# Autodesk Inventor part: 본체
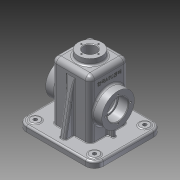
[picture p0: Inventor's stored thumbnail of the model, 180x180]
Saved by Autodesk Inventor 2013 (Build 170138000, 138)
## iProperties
Created: 2016-01
Part Number: 본체
Material: 알루미늄 6061
Document SubType Name: Modeling
Designer: User
Density: 2.71 g/cm^3
Mass: 858.396 g
Surface Area: 910.857 cm^2
Volume: 316.751 cm^3
Author: User
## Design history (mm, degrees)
sketch "스케치1"
  geometry: L1 (-65, -57.5)-(65, -57.5); L2 (65, -57.5)-(65, 57.5); L3 (65, 57.5)-(-65, 57.5); L4 (-65, 57.5)-(-65, -57.5); L5 (-65, -57.5)-(65, 57.5); L6 (65, -57.5)-(-65, 57.5); 1 further point
  constraints: 12 end point, 2 midpoint, 2 parallel, 1 horizontal, 1 perpendicular
  dimensions: "d0" = 130 distance of L2.end L3.end; "d2" = 115 distance of L1.end L2.end
extrude "돌출1" new body sketch "스케치1" distance "d3" = 10; taper "d4" = 0 deg
sketch "스케치2"
  geometry: L1 (-60, -52.5)-(60, -52.5); L2 (60, -52.5)-(60, 52.5); L3 (60, 52.5)-(-60, 52.5); L4 (-60, 52.5)-(-60, -52.5); L5 (-60, -52.5)-(60, 52.5); L6 (60, -52.5)-(-60, 52.5); 1 further point
  constraints: 12 end point, 2 midpoint, 2 parallel, 1 horizontal, 1 perpendicular
  dimensions: "d5" = 120 distance of L2.end L3.end; "d7" = 105 distance of L1.end L2.end
extrude "돌출2" join sketch "스케치2" distance "d8" = 2; taper "d9" = 0 deg
sketch "스케치3"
  geometry: L1 (-32.5, -32.5)-(32.5, -32.5); L2 (32.5, -32.5)-(32.5, 32.5); L3 (32.5, 32.5)-(-32.5, 32.5); L4 (-32.5, 32.5)-(-32.5, -32.5); L5 (-32.5, -32.5)-(32.5, 32.5); L6 (32.5, -32.5)-(-32.5, 32.5); 1 further point
  constraints: 12 end point, 2 midpoint, 2 parallel, 1 horizontal, 1 perpendicular
  dimensions: "d10" = 65 distance of L2.end L3.end; "d12" = 65 distance of L1.end L2.end
extrude "돌출3" join sketch "스케치3" distance "d13" = 98; taper "d14" = 0 deg
sketch "스케치4"
  geometry: C1 r 20 at (0, 0); 1 further point
  constraints: 1 centre point, 1 coincident
  dimensions: "d15" = 40 diameter of C1
extrude "돌출4" join sketch "스케치4" distance "d17" = 10; taper "d18" = 0 deg
feature "면 기울기1" dims angle "d19" = 2.5 deg
sketch "스케치5"
  geometry: C1 r 27.5 at (-43, 32.5); 1 further point
  constraints: 1 centre point, 1 horizontal alignment
  dimensions: "d20" = 55 diameter of C1; "d22" = 53 distance of point (10, 32.5) C1.centre
extrude "돌출5" join sketch "스케치5" distance "d23" = 15; taper "d24" = 0 deg
sketch "스케치7"
  geometry: L1 (32.5, -32.5)-(-32.5, -32.5) reference; L2 (0, 0)-(0, 25.72); L3 (0, 0)-(16.636, 0); C1 r 7.5 at (-50, 42.5); C2 r 7.5 at (50, 42.5); C3 r 7.5 at (-50, -42.5); C4 r 7.5 at (50, -42.5); 1 further point
  constraints: 4 centre point, 4 end point, 3 symmetric about line, 2 perpendicular, 3 other
  dimensions: "d30" = 15 diameter of C1; "d32" = 100 diameter of C1.centre L2; "d33" = 85 diameter of C1.centre L3
extrude "돌출7" join sketch "스케치7" distance "d34" = 1; taper "d35" = 0 deg
hole "구멍1" diameter "d38" = 6; stored, may be unused: countersink angle "d42" = 90 deg, drill point angle "d44" = 118 deg; dims "d36" = 10, "d37" = 10, "d39" = 6, "d40" = 4, "d41" = 2, "d43" = 8
hole "구멍2" diameter "d47" = 6; stored, may be unused: countersink angle "d51" = 90 deg, drill point angle "d53" = 118 deg; dims "d45" = 10, "d46" = 10, "d48" = 6, "d49" = 4, "d50" = 2, "d52" = 8
hole "구멍3" diameter "d56" = 6; stored, may be unused: countersink angle "d60" = 90 deg, drill point angle "d62" = 118 deg; dims "d54" = 10, "d55" = 10, "d57" = 6, "d58" = 4, "d59" = 2, "d61" = 8
hole "구멍4" diameter "d65" = 6; stored, may be unused: countersink angle "d69" = 90 deg, drill point angle "d71" = 118 deg; dims "d63" = 10, "d64" = 10, "d66" = 6, "d67" = 4, "d68" = 2, "d70" = 8
sketch "스케치8"
  geometry: L1 (-27.5, -27.5)-(27.5, -27.5); L2 (27.5, -27.5)-(27.5, 27.5); L3 (27.5, 27.5)-(-27.5, 27.5); L4 (-27.5, 27.5)-(-27.5, -27.5); L5 (-27.5, -27.5)-(27.5, 27.5); L6 (27.5, -27.5)-(-27.5, 27.5); 1 further point
  constraints: 12 end point, 2 midpoint, 2 parallel, 1 horizontal, 1 perpendicular
  dimensions: "d72" = 55 distance of L2.end L3.end; "d74" = 55 distance of L1.end L2.end
extrude "돌출8" cut sketch "스케치8" distance "d75" = 105; taper "d76" = 0 deg
sketch "스케치9"
  geometry: C1 r 20 at (0, 0) reference; C2 r 10.5 at (0, 0)
  constraints: 1 centre point, 1 coincident
  dimensions: "d77" = 21 diameter of C2
extrude "돌출9" cut sketch "스케치9" distance "d79" = 105; taper "d80" = 0 deg
sketch "스케치11"
  geometry: C1 r 27.5 at (0, 0) reference; C2 r 17.5 at (0, 0); 1 further point
  constraints: 1 centre point, 1 coincident
  dimensions: "d84" = 35 diameter of C2
extrude "돌출11" cut sketch "스케치11" distance "d86" = 17; taper "d87" = 0 deg
sketch "스케치12"
  geometry: C1 r 17.5 at (0, 0) reference; C2 r 15 at (0, 0); 1 further point
  constraints: 1 centre point, 1 coincident
  dimensions: "d88" = 30 diameter of C2
extrude "돌출12" cut sketch "스케치12" distance "d90" = 17; taper "d91" = 0 deg
sketch "스케치13" dims "d92" = 29
  geometry: L1 (0, 0)-(0, 16.83); C1 r 20 at (0, 0) reference; 1 further point
  constraints: 2 end point, 1 coincident, 1 point on line, 1 vertical, 1 vertical alignment, 2 other
hole "구멍5" sketch "스케치13" at (0, 14.5) diameter "d94" = 2.459; stored, may be unused: countersink angle "d98" = 90 deg, drill point angle "d100" = 118 deg; dims "d95" = 7, "d96" = 4, "d97" = 2, "d99" = 9
sketch "스케치14" dims "d104" = 42
  geometry: L1 (0, 0)-(-38.866, 0); C1 r 27.5 at (0, 0) reference; 2 further points
  constraints: 2 end point, 1 coincident, 1 horizontal, 1 horizontal alignment, 1 point on line, 2 other
hole "구멍6" sketch "스케치14" at (-21, 0) diameter "d106" = 3.242; stored, may be unused: countersink angle "d110" = 90 deg, drill point angle "d112" = 118 deg; dims "d107" = 8, "d108" = 4, "d109" = 2, "d111" = 10
fillet "모깎기1" dims "d116" = 15
fillet "모깎기2" dims "d117" = 8
fillet "모깎기3" dims "d118" = 10
sketch "스케치15"
  geometry: L1 (-10, 52.5)-(-10, 12.5) reference; A1 r 27.5 centre (55, 32.5) between (82.5, 32.5) and (82.5, 32.5) reference; 2 further points
  constraints: 1 horizontal alignment, 1 other
  dimensions: "d119" = 26 distance from line of L1 point (16, 32.5)
feature "엠보싱1" sketch "스케치15" dims "d10" = 65, "d12" = 65, "d120" = 0.5, "d121" = 0
fillet "모깎기4" dims "d122" = 3
fillet "모깎기5" dims "d123" = 0.3
chamfer "모따기1" distance "d125" = 1; stored, may be unused: second distance "d126" = 2, angle "d127" = 45 deg
fillet "모깎기7" dims "d128" = 3
sketch "스케치16"
  geometry: L1 (28.085, -3)-(39.5, -3); L2 (39.5, 3)-(28.085, 3); L3 (28.085, 3)-(28.085, -3); L4 (28.085, -3)-(39.5, 3); L5 (39.5, -3)-(28.085, 3); L6 (27.5, -27.5)-(27.5, 27.5) reference; A1 r 3 centre (39.5, 0) between (39.5, -3) and (39.5, 3); 2 further points
  constraints: 10 end point, 2 midpoint, 2 point on circle, 2 tangent, 1 centre point, 1 horizontal, 1 horizontal alignment, 1 parallel, 1 perpendicular
  dimensions: "d129" = 15 dimension on A1 L6; "d130" = 6 distance between parallel lines of L1 L2
extrude "돌출13" join sketch "스케치16" distance "d131" = 17; taper "d132" = 0 deg
sketch "스케치17"
  geometry: L1 (47.5, 10)-(31.384, 101.398); L2 (31.384, 101.398)-(31.384, 10); L3 (31.384, 10)-(47.5, 10); L4 (52.236, 10)-(32.764, 10) reference; L5 (57.5, 10)-(57.5, 0) reference; 2 further points
  constraints: 6 end point, 1 midpoint, 1 perpendicular, 1 point on line, 1 vertical
  dimensions: "d134" = 10 distance from line of L5 L1.start; "d135" = 10 deg angle of L1 L5
extrude "돌출14" join sketch "스케치17" stored distance "d136" = 10; taper "d137" = 0 deg
fillet "모깎기9" dims "d138" = 3
fillet "모깎기10" dims "d139" = 3
fillet "모깎기11" dims "d140" = 3
fillet "모깎기12" dims "d141" = 3
fillet "모깎기13" dims "d142" = 1
fillet "모깎기14" dims "d143" = 3
node "솔리드1"
mirror "대칭1"
mirror "대칭4"
pattern_circular "원형 패턴1" dims angle "d102" = 360 deg
pattern_circular "원형 패턴2" dims angle "d114" = 360 deg
mirror "대칭5"
mirror "대칭6"
mirror "대칭7"
